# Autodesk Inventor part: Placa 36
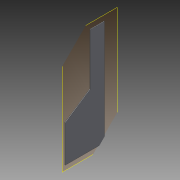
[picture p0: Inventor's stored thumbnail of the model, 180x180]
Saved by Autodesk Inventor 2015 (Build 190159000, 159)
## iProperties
Created: 2015-04
Part Number: Placa 36
Material: Generic
Document SubType Name: Modeling
Designer: suporte
Density: 1 g/cm^3
Appearance: Default
Author: suporte
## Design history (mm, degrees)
workplane "Work Plane1"
sketch "Sketch1"
  geometry: L1 (-600.233, -960.677)-(-600.233, -107.473) reference; L2 (-600.233, -107.473)-(-100.233, 226.027) reference; L3 (-100.233, 226.027)-(-100.233, 1139.323) reference; L4 (-100.233, 1139.323)-(399.767, 1139.323) reference; L5 (399.767, -960.677)-(-600.233, -960.677) reference; L6 (187.267, 1139.323)-(187.267, -960.677) reference; L7 (187.267, 1139.323)-(-100.233, 1139.323); L8 (-100.233, 226.027)-(-100.233, 105.823); L9 (-100.233, 105.823)-(-600.233, -227.677); L10 (-600.233, -960.677)-(-600.233, -227.677); L11 (-600.233, -960.677)-(187.267, -960.677); L12 (199.767, 1139.323)-(199.767, -960.677); L13 (-600.233, -227.677)-(-612.733, -236.014); L14 (-612.733, -960.677)-(-612.733, 1139.323) reference; L15 (-612.733, -960.677)-(-600.233, -960.677); 1 further point
  constraints: 26 end point, 4 collinear, 4 point on line, 3 vertical, 2 horizontal, 2 parallel, 1 perpendicular, 7 other
  dimensions: "d0" = 100 distance between parallel lines of L2 L9; "d3" = 800 distance of L1.start L12.end
extrude "Extrusion1" new body sketch "Sketch1" distance "d1" = 12.5; taper "d2" = 0 deg
body "Solid1"
node "Reference1"
node "Reference2"
